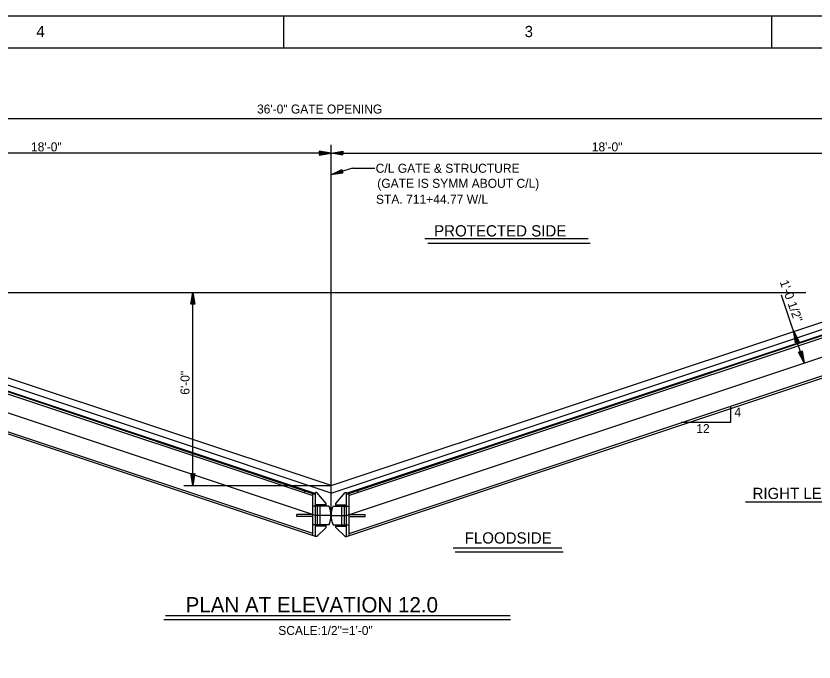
# Model space of a CAD drawing. Extents: x 0.6 to 54, y 0.6 to 38.
# Drawn here: x 17.22 to 33.83, y 24.51 to 37.96 of the extents above; entities that cross this region are included whole.
import ezdxf

# ---------------------------------------------------------------- set-up
doc = ezdxf.new("R2010")
doc.units = 0
for name, color, linetype in [('Level 1', 7, 'Continuous'), ('Level 2', 7, 'Continuous'), ('Level 25', 7, 'Continuous'), ('Level 50', 7, 'Continuous')]:
    doc.layers.add(name, color=color, linetype=linetype)

msp = doc.modelspace()

# ---------------------------------------------------------------- linework, layer by layer
at = {"layer": 'Level 1'}
for p, q in [((22.792, 37.292), (22.792, 37.958)), ((32.958, 37.292), (32.958, 37.958))]:
    msp.add_line(p, q, dxfattribs=at)
for points in [[(0.625, 37.958), (53.958, 37.958), (53.958, 0.625), (0.625, 0.625)], [(2.625, 37.292), (53.292, 37.292), (53.292, 1.292), (2.625, 1.292)]]:
    msp.add_lwpolyline(points, close=True, dxfattribs=at)
at = {"layer": 'Level 25'}
for p, q in [((11.716, 35.824), (35.836, 35.824)), ((23.776, 27.632), (23.776, 35.274)), ((23.776, 27.632), (23.776, 35.274)), ((23.776, 35.101), (11.716, 35.101)), ((23.776, 35.101), (35.836, 35.101)), ((24.22, 34.787), (23.771, 34.653)), ((24.22, 34.787), (24.685, 34.787)), ((25.728, 33.326), (29.131, 33.326)), ((25.789, 33.225), (29.175, 33.225)), ((10.901, 32.182), (23.455, 27.997)), ((10.919, 32.194), (23.441, 28.02)), ((10.94, 32.125), (23.399, 27.972)), ((11.716, 32.199), (33.663, 32.199)), ((20.896, 28.179), (20.896, 32.209)), ((36.651, 32.182), (24.097, 27.997)), ((36.632, 32.194), (24.111, 28.02)), ((36.611, 32.125), (24.153, 27.972)), ((33.628, 30.736), (33.157, 32.148)), ((32.103, 29.503), (32.103, 29.826)), ((31.064, 29.503), (32.103, 29.503)), ((20.709, 28.179), (23.776, 28.179)), ((23.227, 28.072), (23.214, 28.034)), ((23.399, 27.138), (23.399, 28.014)), ((23.441, 28), (23.441, 28.019)), ((23.455, 27.12), (23.455, 28.039)), ((23.483, 28.039), (23.455, 28.039)), ((24.069, 28.039), (24.097, 28.039)), ((24.097, 27.12), (24.097, 28.039)), ((24.111, 28), (24.111, 28.019)), ((24.153, 27.138), (24.153, 28.014)), ((24.325, 28.072), (24.338, 28.034)), ((23.455, 27.754), (23.399, 27.754)), ((23.678, 27.782), (23.455, 27.782)), ((23.734, 27.754), (23.455, 27.754)), ((23.497, 27.363), (23.497, 27.754)), ((23.553, 27.363), (23.553, 27.754)), ((23.678, 27.754), (23.678, 27.81)), ((23.818, 27.754), (24.097, 27.754)), ((23.874, 27.754), (23.874, 27.81)), ((23.874, 27.782), (24.097, 27.782)), ((23.999, 27.363), (23.999, 27.754)), ((24.055, 27.363), (24.055, 27.754)), ((24.097, 27.754), (24.153, 27.754)), ((32.406, 27.844), (34.655, 27.844)), ((23.399, 27.58), (23.064, 27.58)), ((23.064, 27.538), (23.064, 27.58)), ((23.399, 27.538), (23.064, 27.538)), ((23.776, 27.559), (23.455, 27.559)), ((23.776, 27.559), (24.097, 27.559)), ((24.153, 27.58), (24.488, 27.58)), ((24.153, 27.538), (24.488, 27.538)), ((24.488, 27.538), (24.488, 27.58)), ((23.455, 27.363), (23.399, 27.363)), ((23.734, 27.363), (23.455, 27.364)), ((23.678, 27.336), (23.455, 27.336)), ((23.734, 27.363), (23.481, 27.363)), ((23.678, 27.308), (23.678, 27.363)), ((23.678, 27.308), (23.678, 27.363)), ((23.818, 27.363), (24.097, 27.364)), ((23.818, 27.363), (24.071, 27.363)), ((23.874, 27.308), (23.874, 27.363)), ((23.874, 27.308), (23.874, 27.363)), ((23.874, 27.336), (24.097, 27.336)), ((24.097, 27.363), (24.153, 27.363)), ((23.483, 27.12), (23.455, 27.12)), ((24.069, 27.12), (24.097, 27.12)), ((26.319, 26.882), (28.579, 26.882)), ((26.36, 26.8), (28.609, 26.8)), ((20.327, 25.477), (27.503, 25.477)), ((20.297, 25.391), (27.515, 25.391))]:
    msp.add_line(p, q, dxfattribs=at)
for centre, start, end in [((23.299, 27.559), 335.8105, 24.1895), ((24.253, 27.559), 155.8105, 204.1895)]:
    msp.add_arc(centre, 0.477, start, end, dxfattribs=at)
at = {"layer": 'Level 50'}
for p, q in [((23.707, 35.101), (23.707, 35.101)), ((23.712, 35.101), (23.712, 35.101)), ((23.717, 35.101), (23.717, 35.101)), ((23.717, 35.101), (23.717, 35.101)), ((23.721, 35.101), (23.721, 35.101)), ((23.776, 35.101), (23.776, 35.101)), ((23.776, 35.101), (23.776, 35.101)), ((23.831, 35.101), (23.831, 35.101)), ((23.835, 35.101), (23.835, 35.101)), ((23.835, 35.101), (23.835, 35.101)), ((23.84, 35.101), (23.84, 35.101)), ((23.845, 35.101), (23.845, 35.101)), ((23.771, 34.653), (23.771, 34.653)), ((23.837, 34.673), (23.837, 34.673)), ((23.776, 28.023), (11.246, 32.199)), ((23.776, 28.179), (11.716, 32.199)), ((20.896, 32.209), (20.896, 32.209)), ((20.896, 32.14), (20.896, 32.14)), ((23.776, 28.179), (35.836, 32.199)), ((23.776, 28.023), (36.305, 32.199)), ((23.455, 27.559), (10.216, 31.972)), ((24.097, 27.559), (37.336, 31.972)), ((23.399, 27.182), (10.703, 31.414)), ((24.153, 27.182), (36.848, 31.414)), ((23.455, 27.12), (10.637, 31.392)), ((24.097, 27.12), (36.915, 31.392)), ((33.407, 31.399), (33.407, 31.399)), ((33.429, 31.334), (33.429, 31.334)), ((33.606, 30.802), (33.606, 30.802)), ((33.628, 30.736), (33.628, 30.736)), ((20.896, 28.249), (20.896, 28.249)), ((20.896, 28.179), (20.896, 28.179)), ((23.678, 27.81), (23.483, 28.039)), ((23.874, 27.81), (24.069, 28.039)), ((23.483, 27.12), (23.678, 27.308)), ((24.069, 27.12), (23.874, 27.308))]:
    msp.add_line(p, q, dxfattribs=at)
for points in [[(23.527, 35.06), (23.776, 35.101), (23.527, 35.142), (23.527, 35.072), (23.707, 35.101), (23.537, 35.129), (23.537, 35.084), (23.64, 35.101), (23.548, 35.116), (23.548, 35.097), (23.571, 35.101)], [(23.701, 35.099), (23.717, 35.101), (23.701, 35.104), (23.701, 35.099), (23.712, 35.101), (23.702, 35.103), (23.702, 35.1), (23.708, 35.101), (23.702, 35.102), (23.702, 35.101), (23.704, 35.101)], [(23.732, 35.104), (23.717, 35.101), (23.732, 35.099), (23.732, 35.103), (23.721, 35.101), (23.731, 35.099), (23.731, 35.102), (23.725, 35.101), (23.731, 35.1), (23.731, 35.101), (23.729, 35.101)], [(24.025, 35.06), (23.776, 35.101), (24.025, 35.142), (24.025, 35.072), (23.845, 35.101), (24.015, 35.129), (24.015, 35.084), (23.912, 35.101), (24.004, 35.116), (24.004, 35.097), (23.981, 35.101)], [(23.82, 35.104), (23.835, 35.101), (23.82, 35.099), (23.82, 35.103), (23.831, 35.101), (23.82, 35.099), (23.82, 35.102), (23.827, 35.101), (23.821, 35.1), (23.821, 35.101), (23.822, 35.101)], [(23.851, 35.099), (23.835, 35.101), (23.851, 35.104), (23.851, 35.099), (23.84, 35.101), (23.85, 35.103), (23.85, 35.1), (23.844, 35.101), (23.85, 35.102), (23.85, 35.101), (23.848, 35.101)], [(24.023, 34.685), (23.771, 34.653), (23.999, 34.765), (24.019, 34.697), (23.837, 34.673), (23.992, 34.749), (24.006, 34.705), (23.902, 34.692), (23.986, 34.733), (23.991, 34.715), (23.968, 34.712)], [(20.854, 31.96), (20.896, 32.209), (20.937, 31.96), (20.866, 31.96), (20.896, 32.14), (20.924, 31.97), (20.878, 31.97), (20.896, 32.073), (20.91, 31.981), (20.892, 31.981), (20.896, 32.004)], [(33.446, 31.15), (33.407, 31.399), (33.525, 31.176), (33.458, 31.154), (33.429, 31.334), (33.509, 31.182), (33.466, 31.167), (33.45, 31.27), (33.493, 31.188), (33.475, 31.182), (33.472, 31.205)], [(33.588, 30.985), (33.628, 30.736), (33.51, 30.959), (33.577, 30.982), (33.606, 30.802), (33.526, 30.953), (33.569, 30.968), (33.585, 30.865), (33.542, 30.947), (33.56, 30.953), (33.563, 30.931)], [(20.937, 28.429), (20.896, 28.179), (20.854, 28.429), (20.925, 28.429), (20.896, 28.249), (20.868, 28.418), (20.913, 28.418), (20.896, 28.315), (20.881, 28.407), (20.9, 28.407), (20.896, 28.385)]]:
    msp.add_lwpolyline(points, dxfattribs=at)

# ---------------------------------------------------------------- texts
at = {"layer": 'Level 1'}
for s, p in [('4', (17.641, 37.518)), ('3', (27.807, 37.518))]:
    msp.add_text(s, height=0.234, dxfattribs=at).set_placement(p)
at = {"layer": 'Level 2'}
msp.add_text('PLAN AT ELEVATION 12.0', height=0.32, dxfattribs=at).set_placement((20.748, 25.538))
at = {"layer": 'Level 25'}
for s, height, p in [('36\'-0" GATE OPENING', 0.18667, (22.236, 35.927)), ('18\'-0"', 0.1876, (17.529, 35.139)), ('18\'-0"', 0.1876, (29.205, 35.139)), ('C/L GATE & STRUCTURE', 0.1876, (24.706, 34.693)), ('(GATE IS SYMM ABOUT C/L)', 0.1876, (24.739, 34.38)), ('STA. 711+44.77 W/L', 0.1876, (24.712, 34.048)), ('PROTECTED SIDE', 0.2345, (25.923, 33.367)), ('4', 0.187, (32.175, 29.616)), ('12', 0.1867, (31.382, 29.273)), ('RIGHT LEAF', 0.2333, (32.554, 27.901)), ('FLOODSIDE', 0.2345, (26.559, 26.973)), ('SCALE:1/2"=1\'-0"', 0.18667, (22.678, 25.07))]:
    msp.add_text(s, height=height, dxfattribs=at).set_placement(p)
for s, rotation, p in [('1\'-0 1/2"', 290, (33.116, 32.421)), ('6\'-0"', 90, (20.829, 30.072))]:
    msp.add_text(s, height=0.1867, rotation=rotation, dxfattribs=at).set_placement(p)

doc.saveas('drawing.dxf')
